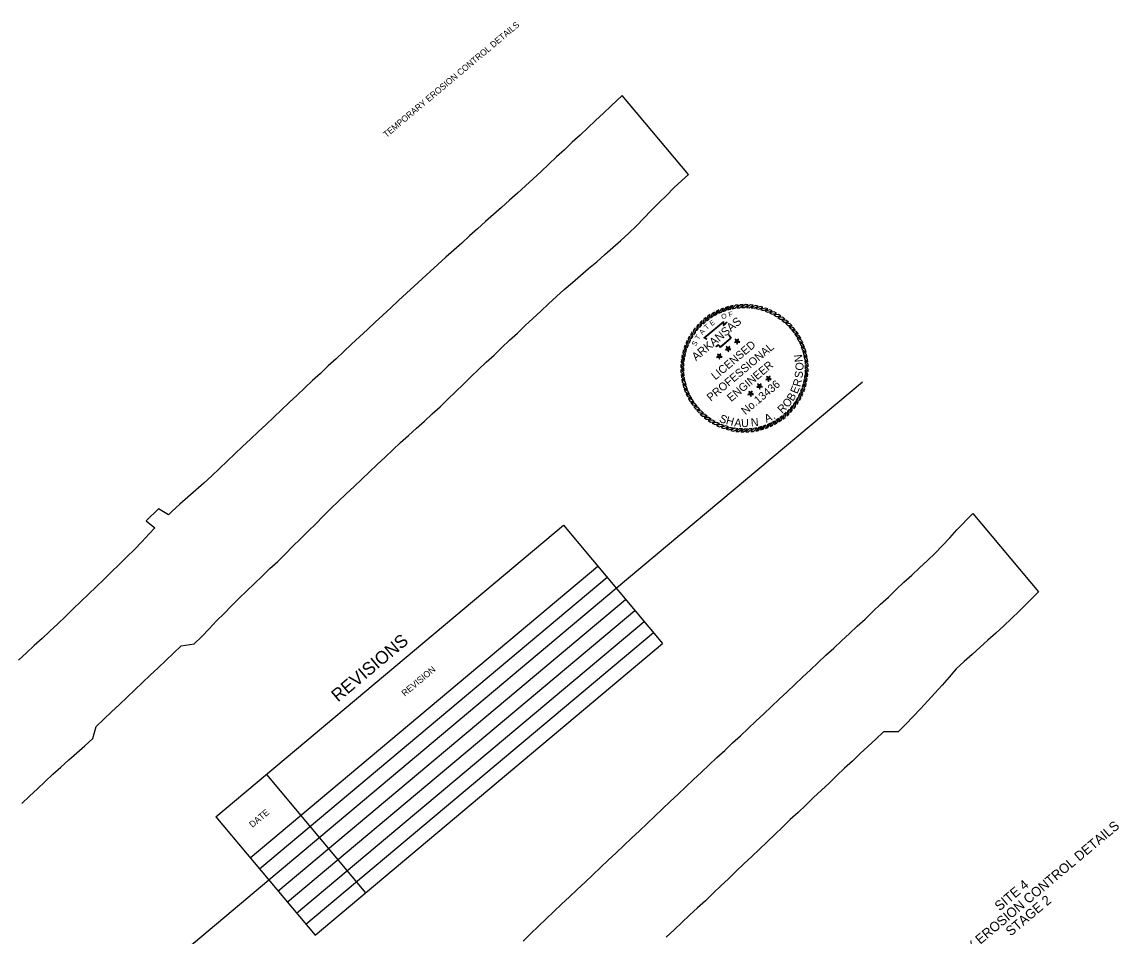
# Model space of a CAD drawing. Extents: x 1430270 to 1431940, y 1964631 to 1966264.
# Drawn here: x 1430913 to 1431940, y 1965408 to 1966264 of the extents above; entities that cross this region are included whole.
import ezdxf

# ---------------------------------------------------------------- set-up
doc = ezdxf.new("R2010")
doc.units = 0
for name, color, linetype in [('1', 7, 'Continuous'), ('60', 7, 'Continuous'), ('Default', 7, 'Continuous'), ('G-ANNO-SYMB', 7, 'Continuous'), ('R_NO PLOT', 7, 'Continuous')]:
    doc.layers.add(name, color=color, linetype=linetype)

msp = doc.modelspace()

# ---------------------------------------------------------------- linework, layer by layer
at = {"layer": '1'}
for p, q in [((1431469.3, 1965733.3), (1431699.9, 1965926.7)), ((1430924.6, 1965276.1), (1431143.8, 1965460.1))]:
    msp.add_line(p, q, dxfattribs=at)
at = {"layer": 'Default'}
for p, q in [((1431094.3, 1965519.1), (1431419.9, 1965792.3)), ((1431419.9, 1965792.3), (1431512.7, 1965681.6)), ((1431126.4, 1965480.8), (1431452, 1965754)), ((1431135.1, 1965470.4), (1431460.7, 1965743.6)), ((1431143.8, 1965460.1), (1431469.3, 1965733.3)), ((1431152.5, 1965449.7), (1431478, 1965722.9)), ((1431152.5, 1965449.7), (1431478, 1965722.9)), ((1431161.1, 1965439.4), (1431486.7, 1965712.6)), ((1431169.8, 1965429.1), (1431495.4, 1965702.2)), ((1431178.5, 1965418.7), (1431504.1, 1965691.9)), ((1431187.2, 1965408.4), (1431512.7, 1965681.6)), ((1431141.6, 1965558.8), (1431234.5, 1965448.1)), ((1431094.3, 1965519.1), (1431187.2, 1965408.4))]:
    msp.add_line(p, q, dxfattribs=at)
at = {"layer": 'G-ANNO-SYMB'}
for points in [[(1431561.3, 1965992), (1431559.1, 1965990.7), (1431557.5, 1965986.5), (1431559.8, 1965988)], [(1431565.5, 1965994), (1431563.2, 1965992.9), (1431561.3, 1965988.8), (1431563.7, 1965990.1)], [(1431569.9, 1965995.7), (1431567.5, 1965994.8), (1431565.2, 1965990.9), (1431567.8, 1965992)], [(1431574.4, 1965997.1), (1431571.9, 1965996.4), (1431569.3, 1965992.6), (1431572, 1965993.5)], [(1431579, 1965998.1), (1431576.5, 1965997.6), (1431573.6, 1965994), (1431576.3, 1965994.8)], [(1431583.6, 1965998.7), (1431581.1, 1965998.4), (1431577.9, 1965995.1), (1431580.6, 1965995.6)], [(1431588.3, 1965999), (1431585.7, 1965998.9), (1431582.3, 1965995.9), (1431585.1, 1965996.1)], [(1431593, 1965998.9), (1431590.4, 1965999), (1431586.8, 1965996.2), (1431589.5, 1965996.3)], [(1431597.6, 1965998.5), (1431595.1, 1965998.8), (1431591.2, 1965996.3), (1431594, 1965996.1)], [(1431602.2, 1965997.6), (1431599.7, 1965998.1), (1431595.7, 1965996), (1431598.5, 1965995.6)], [(1431606.8, 1965996.5), (1431604.3, 1965997.2), (1431600.1, 1965995.3), (1431602.8, 1965994.7)], [(1431611.2, 1965994.9), (1431608.8, 1965995.8), (1431604.5, 1965994.3), (1431607.1, 1965993.5)], [(1431615.5, 1965993.1), (1431613.2, 1965994.1), (1431608.7, 1965992.9), (1431611.3, 1965991.9)], [(1431619.6, 1965990.9), (1431617.4, 1965992.1), (1431612.9, 1965991.3), (1431615.4, 1965990.1)], [(1431546.5, 1965980.7), (1431544.7, 1965978.8), (1431544.5, 1965974.3), (1431546.2, 1965976.4)], [(1431549.8, 1965984), (1431547.9, 1965982.2), (1431547.4, 1965977.7), (1431549.3, 1965979.7)], [(1431553.5, 1965986.9), (1431551.4, 1965985.3), (1431550.5, 1965980.9), (1431552.6, 1965982.7)], [(1431557.3, 1965989.6), (1431555.2, 1965988.2), (1431553.9, 1965983.8), (1431556.1, 1965985.5)], [(1431623.6, 1965988.3), (1431621.4, 1965989.7), (1431616.9, 1965989.3), (1431619.3, 1965987.9)], [(1431627.3, 1965985.5), (1431625.3, 1965987.1), (1431620.7, 1965987), (1431623, 1965985.4)], [(1431630.8, 1965982.4), (1431628.9, 1965984.1), (1431624.4, 1965984.4), (1431626.5, 1965982.6)], [(1431634.1, 1965979), (1431632.3, 1965980.9), (1431627.8, 1965981.5), (1431629.8, 1965979.6)], [(1431540.5, 1965973.5), (1431539.1, 1965971.3), (1431539.6, 1965966.8), (1431541, 1965969.2)], [(1431543.3, 1965977.2), (1431541.8, 1965975.2), (1431541.9, 1965970.6), (1431543.5, 1965972.9)], [(1431637, 1965975.4), (1431635.4, 1965977.4), (1431631, 1965978.4), (1431632.8, 1965976.3)], [(1431639.7, 1965971.5), (1431638.3, 1965973.7), (1431633.9, 1965975), (1431635.6, 1965972.8)], [(1431642.1, 1965967.5), (1431640.8, 1965969.7), (1431636.6, 1965971.4), (1431638.1, 1965969.1)], [(1431533.9, 1965961.1), (1431533, 1965958.7), (1431534.6, 1965954.4), (1431535.3, 1965957)], [(1431535.8, 1965965.4), (1431534.7, 1965963.1), (1431535.9, 1965958.6), (1431536.9, 1965961.2)], [(1431538, 1965969.5), (1431536.7, 1965967.3), (1431537.6, 1965962.8), (1431538.8, 1965965.3)], [(1431574.2, 1965957.6), (1431574.1, 1965958.6), (1431572.4, 1965959.7), (1431573.2, 1965957.8)], [(1431574.2, 1965957.6), (1431575.2, 1965958), (1431575.6, 1965959.9), (1431574.1, 1965958.6)], [(1431582.6, 1965964.6), (1431581.5, 1965964.8), (1431580, 1965963.6), (1431582, 1965963.7)], [(1431582.6, 1965964.6), (1431582.5, 1965965.6), (1431580.8, 1965966.7), (1431581.5, 1965964.8)], [(1431582.6, 1965964.6), (1431582, 1965963.7), (1431582.7, 1965961.9), (1431583.2, 1965963.8)], [(1431582.6, 1965964.6), (1431583.5, 1965965), (1431584, 1965966.9), (1431582.5, 1965965.6)], [(1431582.6, 1965964.6), (1431583.2, 1965963.8), (1431585.2, 1965963.9), (1431583.5, 1965965)], [(1431644.1, 1965963.3), (1431643, 1965965.6), (1431638.9, 1965967.6), (1431640.2, 1965965.2)], [(1431645.8, 1965958.9), (1431644.9, 1965961.3), (1431641, 1965963.6), (1431642.1, 1965961.1)], [(1431531.2, 1965952.1), (1431530.7, 1965949.6), (1431532.9, 1965945.6), (1431533.2, 1965948.4)], [(1431532.4, 1965956.7), (1431531.7, 1965954.2), (1431533.5, 1965950), (1431534.1, 1965952.7)], [(1431565.8, 1965950.6), (1431564.8, 1965950.8), (1431563.3, 1965949.5), (1431565.3, 1965949.7)], [(1431565.8, 1965950.6), (1431565.8, 1965951.6), (1431564.1, 1965952.6), (1431564.8, 1965950.8)], [(1431565.8, 1965950.6), (1431565.3, 1965949.7), (1431566, 1965947.8), (1431566.5, 1965949.8)], [(1431565.8, 1965950.6), (1431566.8, 1965951), (1431567.3, 1965952.9), (1431565.8, 1965951.6)], [(1431565.8, 1965950.6), (1431566.5, 1965949.8), (1431568.5, 1965949.9), (1431566.8, 1965951)], [(1431574.2, 1965957.6), (1431573.2, 1965957.8), (1431571.7, 1965956.6), (1431573.6, 1965956.7)], [(1431574.2, 1965957.6), (1431573.6, 1965956.7), (1431574.4, 1965954.9), (1431574.9, 1965956.8)], [(1431574.2, 1965957.6), (1431574.9, 1965956.8), (1431576.8, 1965956.9), (1431575.2, 1965958)], [(1431647.2, 1965954.4), (1431646.5, 1965956.9), (1431642.7, 1965959.5), (1431643.6, 1965956.9)], [(1431648.2, 1965949.9), (1431647.7, 1965952.4), (1431644.1, 1965955.3), (1431644.8, 1965952.6)], [(1431648.8, 1965945.2), (1431648.5, 1965947.8), (1431645.2, 1965950.9), (1431645.7, 1965948.2)], [(1431529.9, 1965942.9), (1431529.8, 1965940.3), (1431532.6, 1965936.7), (1431532.5, 1965939.5)], [(1431530.4, 1965947.5), (1431530.1, 1965945), (1431532.6, 1965941.2), (1431532.7, 1965943.9)], [(1431649.1, 1965940.6), (1431649, 1965943.1), (1431646, 1965946.5), (1431646.2, 1965943.8)], [(1431649, 1965935.9), (1431649.1, 1965938.4), (1431646.3, 1965942.1), (1431646.4, 1965939.3)], [(1431529.8, 1965938.2), (1431529.9, 1965935.6), (1431533, 1965932.2), (1431532.7, 1965935)], [(1431530.1, 1965933.5), (1431530.4, 1965931), (1431533.7, 1965927.8), (1431533.2, 1965930.5)], [(1431530.7, 1965928.9), (1431531.2, 1965926.4), (1431534.8, 1965923.5), (1431534.1, 1965926.2)], [(1431611.9, 1965929.6), (1431610.9, 1965929.8), (1431609.4, 1965928.6), (1431611.4, 1965928.7)], [(1431611.9, 1965929.6), (1431611.8, 1965930.6), (1431610.2, 1965931.7), (1431610.9, 1965929.8)], [(1431611.9, 1965929.6), (1431611.4, 1965928.7), (1431612.1, 1965926.9), (1431612.6, 1965928.8)], [(1431611.9, 1965929.6), (1431612.9, 1965930), (1431613.4, 1965931.9), (1431611.8, 1965930.6)], [(1431611.9, 1965929.6), (1431612.6, 1965928.8), (1431614.6, 1965928.9), (1431612.9, 1965930)], [(1431647.7, 1965926.6), (1431648.2, 1965929.1), (1431646.1, 1965933.1), (1431645.7, 1965930.4)], [(1431648.6, 1965931.2), (1431648.9, 1965933.8), (1431646.4, 1965937.6), (1431646.2, 1965934.8)], [(1431531.7, 1965924.3), (1431532.4, 1965921.8), (1431536.2, 1965919.2), (1431535.3, 1965921.9)], [(1431533.1, 1965919.8), (1431534, 1965917.4), (1431538, 1965915.1), (1431536.8, 1965917.7)], [(1431603.6, 1965922.6), (1431602.6, 1965922.8), (1431601, 1965921.6), (1431603, 1965921.7)], [(1431603.6, 1965922.6), (1431603.5, 1965923.6), (1431601.8, 1965924.7), (1431602.6, 1965922.8)], [(1431603.6, 1965922.6), (1431603, 1965921.7), (1431603.8, 1965919.9), (1431604.2, 1965921.8)], [(1431603.6, 1965922.6), (1431604.5, 1965923), (1431605, 1965924.9), (1431603.5, 1965923.6)], [(1431603.6, 1965922.6), (1431604.2, 1965921.8), (1431606.2, 1965921.9), (1431604.5, 1965923)], [(1431643.2, 1965913.3), (1431644.2, 1965915.7), (1431643, 1965920.1), (1431642, 1965917.5)], [(1431645, 1965917.6), (1431645.9, 1965920.1), (1431644.4, 1965924.4), (1431643.6, 1965921.7)], [(1431646.6, 1965922.1), (1431647.3, 1965924.5), (1431645.4, 1965928.7), (1431644.8, 1965926)], [(1431534.8, 1965915.5), (1431535.9, 1965913.1), (1431540, 1965911.2), (1431538.7, 1965913.6)], [(1431536.9, 1965911.2), (1431538.1, 1965909), (1431542.4, 1965907.4), (1431540.9, 1965909.7)], [(1431595.2, 1965915.6), (1431594.2, 1965915.8), (1431592.7, 1965914.5), (1431594.7, 1965914.7)], [(1431595.2, 1965915.6), (1431595.1, 1965916.6), (1431593.5, 1965917.7), (1431594.2, 1965915.8)], [(1431595.2, 1965915.6), (1431594.7, 1965914.7), (1431595.4, 1965912.8), (1431595.9, 1965914.8)], [(1431595.2, 1965915.6), (1431596.2, 1965916), (1431596.7, 1965917.9), (1431595.1, 1965916.6)], [(1431595.2, 1965915.6), (1431595.9, 1965914.8), (1431597.9, 1965914.9), (1431596.2, 1965916)], [(1431638.4, 1965905.3), (1431639.8, 1965907.4), (1431639.4, 1965912), (1431638, 1965909.6)], [(1431640.9, 1965909.2), (1431642.2, 1965911.5), (1431641.4, 1965916), (1431640.2, 1965913.5)], [(1431539.2, 1965907.2), (1431540.7, 1965905.1), (1431545, 1965903.8), (1431543.4, 1965906)], [(1431541.9, 1965903.4), (1431543.5, 1965901.3), (1431548, 1965900.4), (1431546.1, 1965902.5)], [(1431544.9, 1965899.7), (1431546.6, 1965897.9), (1431551.2, 1965897.3), (1431549.2, 1965899.2)], [(1431629.1, 1965894.8), (1431631, 1965896.5), (1431631.6, 1965901.1), (1431629.7, 1965899.1)], [(1431632.5, 1965898), (1431634.2, 1965899.9), (1431634.5, 1965904.5), (1431632.7, 1965902.3)], [(1431635.6, 1965901.5), (1431637.2, 1965903.6), (1431637.1, 1965908.1), (1431635.5, 1965905.8)], [(1431548.1, 1965896.4), (1431550, 1965894.6), (1431554.6, 1965894.4), (1431552.4, 1965896.1)], [(1431551.6, 1965893.2), (1431553.6, 1965891.7), (1431558.2, 1965891.8), (1431555.9, 1965893.4)], [(1431555.4, 1965890.4), (1431557.5, 1965889), (1431562.1, 1965889.5), (1431559.7, 1965890.9)], [(1431559.3, 1965887.9), (1431561.6, 1965886.6), (1431566.1, 1965887.5), (1431563.6, 1965888.7)], [(1431609, 1965883), (1431611.4, 1965883.9), (1431613.7, 1965887.9), (1431611.2, 1965886.7)], [(1431613.4, 1965884.7), (1431615.7, 1965885.8), (1431617.7, 1965889.9), (1431615.2, 1965888.6)], [(1431617.6, 1965886.8), (1431619.8, 1965888), (1431621.5, 1965892.3), (1431619.1, 1965890.8)], [(1431621.6, 1965889.1), (1431623.8, 1965890.6), (1431625.1, 1965894.9), (1431622.9, 1965893.3)], [(1431625.5, 1965891.8), (1431627.5, 1965893.4), (1431628.4, 1965897.9), (1431626.4, 1965896)], [(1431563.4, 1965885.7), (1431565.8, 1965884.6), (1431570.2, 1965885.8), (1431567.6, 1965886.8)], [(1431567.7, 1965883.8), (1431570.1, 1965882.9), (1431574.5, 1965884.5), (1431571.8, 1965885.3)], [(1431572.2, 1965882.3), (1431574.6, 1965881.6), (1431578.8, 1965883.4), (1431576.1, 1965884)], [(1431576.7, 1965881.1), (1431579.2, 1965880.6), (1431583.2, 1965882.8), (1431580.5, 1965883.2)], [(1431581.3, 1965880.3), (1431583.9, 1965880), (1431587.7, 1965882.5), (1431584.9, 1965882.6)], [(1431586, 1965879.8), (1431588.5, 1965879.7), (1431592.2, 1965882.5), (1431589.4, 1965882.4)], [(1431590.7, 1965879.7), (1431593.2, 1965879.8), (1431596.6, 1965882.9), (1431593.9, 1965882.6)], [(1431595.3, 1965880), (1431597.9, 1965880.3), (1431601, 1965883.6), (1431598.3, 1965883.1)], [(1431600, 1965880.6), (1431602.5, 1965881.2), (1431605.4, 1965884.7), (1431602.7, 1965884)], [(1431604.5, 1965881.7), (1431607, 1965882.4), (1431609.6, 1965886.1), (1431607, 1965885.2)]]:
    msp.add_lwpolyline(points, close=True, dxfattribs=at)
for points in [[(1431554.3, 1965966.4), (1431551.3, 1965967.8), (1431569.7, 1965983.3), (1431569.8, 1965980.1), (1431571.1, 1965981.1), (1431572.1, 1965982), (1431573.2, 1965982.8)], [(1431554.5, 1965966.7), (1431552, 1965967.9), (1431569.4, 1965982.5), (1431569.5, 1965979.3), (1431571.3, 1965980.8), (1431572.3, 1965981.7), (1431573.4, 1965982.5)], [(1431575.3, 1965970.8), (1431575.2, 1965970.3), (1431575.4, 1965969.8), (1431576.1, 1965968.8), (1431577.1, 1965967.5), (1431566.9, 1965958.9), (1431565.4, 1965960.6), (1431565.1, 1965961), (1431564.6, 1965960.7), (1431563.1, 1965959.5), (1431562.5, 1965959.7)], [(1431574.9, 1965970.9), (1431574.8, 1965970.2), (1431575, 1965969.6), (1431575.8, 1965968.5), (1431576.6, 1965967.6), (1431566.9, 1965959.4), (1431565.7, 1965960.8), (1431565.2, 1965961.4), (1431564.4, 1965961.1), (1431563, 1965959.9), (1431562.6, 1965960.1)]]:
    msp.add_lwpolyline(points, dxfattribs=at)
at = {"layer": 'R_NO PLOT'}
msp.add_line((1431049.8, 1965802.1), (1431040.7, 1965807.8), dxfattribs=at)
for points in [[(1431537, 1966121), (1431474.9, 1966194.9), (1431464.6, 1966185.2), (1431457.3, 1966178.3), (1431450, 1966171.5), (1431442.7, 1966164.6), (1431435.4, 1966157.8), (1431428.1, 1966151), (1431420.8, 1966144.1), (1431413.5, 1966137.3), (1431406.2, 1966130.5), (1431398.9, 1966123.7), (1431391.5, 1966116.9), (1431384.2, 1966110.1), (1431376.8, 1966103.4), (1431369.3, 1966096.7), (1431361.9, 1966090.1), (1431354.4, 1966083.4), (1431346.9, 1966076.7), (1431339.4, 1966070.1), (1431332, 1966063.4), (1431324.6, 1966056.7), (1431317.1, 1966050.1), (1431309.7, 1966043.4), (1431302.2, 1966036.7), (1431294.9, 1966029.9), (1431287.5, 1966023.1), (1431280.2, 1966016.3), (1431272.8, 1966009.6), (1431265.5, 1966002.8), (1431258.2, 1965996), (1431250.8, 1965989.2), (1431243.5, 1965982.4), (1431236.2, 1965975.6), (1431228.8, 1965968.8), (1431221.4, 1965962), (1431214.1, 1965955.2), (1431206.9, 1965948.3), (1431199.5, 1965941.6), (1431192.3, 1965934.6), (1431184.9, 1965927.8), (1431177.7, 1965920.9), (1431170.4, 1965914.1), (1431163.1, 1965907.3), (1431155.9, 1965900.4), (1431148.6, 1965893.5), (1431141.3, 1965886.7), (1431134, 1965879.8), (1431126.7, 1965873), (1431119.4, 1965866.1), (1431112.2, 1965859.3), (1431104.9, 1965852.4), (1431097.6, 1965845.5), (1431090.4, 1965838.7), (1431083.1, 1965831.8), (1431075.7, 1965825.1), (1431068.1, 1965818.6), (1431060.5, 1965812), (1431053.1, 1965805.3), (1431049.8, 1965802.1)], [(1431061.9, 1965679.5), (1431074, 1965681.2), (1431081.2, 1965688.2), (1431088.1, 1965695.4), (1431095, 1965702.7), (1431102.1, 1965709.8), (1431109.1, 1965716.9), (1431116.1, 1965724), (1431123.3, 1965731), (1431130.6, 1965737.8), (1431137.8, 1965744.8), (1431145, 1965751.7), (1431152.3, 1965758.5), (1431159.4, 1965765.6), (1431166.5, 1965772.6), (1431173.7, 1965779.6), (1431180.7, 1965786.7), (1431187.8, 1965793.8), (1431194.9, 1965800.8), (1431202, 1965807.9), (1431209.2, 1965814.8), (1431216.5, 1965821.7), (1431223.7, 1965828.5), (1431231, 1965835.4), (1431238.3, 1965842.3), (1431245.5, 1965849.2), (1431252.8, 1965856), (1431260.1, 1965862.9), (1431267.4, 1965869.7), (1431274.7, 1965876.5), (1431282.1, 1965883.2), (1431289.6, 1965889.9), (1431297, 1965896.6), (1431304.3, 1965903.4), (1431311.5, 1965910.4), (1431318.8, 1965917.3), (1431325.9, 1965924.2), (1431333.1, 1965931.2), (1431340.4, 1965938.1), (1431347.6, 1965945), (1431354.9, 1965951.8), (1431362.1, 1965958.7), (1431369.4, 1965965.6), (1431376.7, 1965972.4), (1431384, 1965979.3), (1431391.3, 1965986.1), (1431398.6, 1965993), (1431405.9, 1965999.8), (1431413.3, 1966006.5), (1431420.7, 1966013.2), (1431428.3, 1966019.7), (1431435.8, 1966026.4), (1431443.4, 1966032.9), (1431451.3, 1966039.1), (1431458.7, 1966045.8), (1431466.2, 1966052.5), (1431473.6, 1966059.1), (1431481.1, 1966065.8), (1431488.2, 1966072.9), (1431495.1, 1966080.1), (1431502.2, 1966087.2), (1431509.3, 1966094.2), (1431516.3, 1966101.3), (1431523.4, 1966108.4), (1431530.7, 1966115.2), (1431537, 1966121)], [(1431040.7, 1965807.8), (1431028.9, 1965796.6), (1431037, 1965789.8)], [(1431382.1, 1965402.9), (1431389.2, 1965409.9), (1431396.5, 1965416.8), (1431403.7, 1965423.7), (1431410.9, 1965430.7), (1431418.2, 1965437.5), (1431425.5, 1965444.3), (1431432.8, 1965451.1), (1431440.1, 1965458), (1431447.4, 1965464.9), (1431454.6, 1965471.7), (1431461.9, 1965478.6), (1431469.2, 1965485.4), (1431476.5, 1965492.3), (1431483.7, 1965499.2), (1431491, 1965506.1), (1431498.2, 1965513), (1431505.5, 1965519.8), (1431512.7, 1965526.7), (1431520, 1965533.6), (1431527.3, 1965540.5), (1431534.5, 1965547.4), (1431541.8, 1965554.2), (1431549.1, 1965561), (1431556.4, 1965567.9), (1431563.7, 1965574.7), (1431571, 1965581.5), (1431578.3, 1965588.4), (1431585.6, 1965595.2), (1431592.9, 1965602.1), (1431600.2, 1965608.9), (1431607.5, 1965615.7), (1431614.8, 1965622.6), (1431622, 1965629.4), (1431629.3, 1965636.3), (1431636.6, 1965643.2), (1431643.9, 1965650), (1431651.2, 1965656.9), (1431658.5, 1965663.7), (1431665.8, 1965670.5), (1431673.1, 1965677.3), (1431680.4, 1965684.1), (1431687.8, 1965690.9), (1431695.1, 1965697.7), (1431702.4, 1965704.5), (1431709.6, 1965711.5), (1431716.9, 1965718.3), (1431724.3, 1965725.1), (1431731.5, 1965732.1), (1431738.6, 1965739), (1431746.1, 1965745.7), (1431753.5, 1965752.4), (1431760.8, 1965759.2), (1431768.1, 1965766.1), (1431775, 1965773.3), (1431781.9, 1965780.6), (1431788.5, 1965788.1), (1431803.3, 1965803.5), (1431864.9, 1965730.1)], [(1431037, 1965789.8), (1431031.7, 1965784.2), (1431024.9, 1965776.9), (1431018, 1965769.7), (1431010.8, 1965762.7), (1431003.6, 1965755.7), (1430996.5, 1965748.7), (1430989.4, 1965741.6), (1430982.2, 1965734.7), (1430975.1, 1965727.7), (1430967.8, 1965720.8), (1430960.6, 1965713.9), (1430953.4, 1965706.9), (1430946.2, 1965700.1), (1430938.8, 1965693.2), (1430931.5, 1965686.4), (1430924.2, 1965679.7), (1430916.8, 1965672.9), (1430909.5, 1965666.1)], [(1431864.9, 1965730.1), (1431853.9, 1965719), (1431846.7, 1965712), (1431839.5, 1965705.1), (1431832.3, 1965698.1), (1431824.9, 1965691.4), (1431817.5, 1965684.7), (1431810.1, 1965678), (1431802.6, 1965671.3), (1431795.1, 1965664.7), (1431787.7, 1965658), (1431781.3, 1965650.2), (1431774.6, 1965642.7), (1431767.9, 1965635.2), (1431761.2, 1965627.8), (1431754.3, 1965620.5), (1431747.5, 1965613.1), (1431740.6, 1965605.9), (1431733.4, 1965599), (1431719.6, 1965599)], [(1430982.1, 1965603.8), (1430989.3, 1965610.7), (1430996.6, 1965617.6), (1431003.9, 1965624.4), (1431011.1, 1965631.3), (1431018.4, 1965638.2), (1431025.7, 1965645.1), (1431032.9, 1965651.9), (1431040.2, 1965658.8), (1431047.4, 1965665.7), (1431054.7, 1965672.6), (1431061.9, 1965679.5)], [(1430912.7, 1965531.7), (1430919.8, 1965538.7), (1430927.1, 1965545.5), (1430934.4, 1965552.4), (1430941.7, 1965559.1), (1430949.2, 1965565.8), (1430956.6, 1965572.5), (1430964.1, 1965579.2), (1430971.6, 1965585.8), (1430979, 1965592.5), (1430982.1, 1965603.8)], [(1431719.6, 1965599), (1431712.4, 1965592.1), (1431705.1, 1965585.2), (1431697.8, 1965578.4), (1431690.5, 1965571.5), (1431683.3, 1965564.7), (1431676, 1965557.8), (1431668.7, 1965550.9), (1431661.5, 1965544.1), (1431654.2, 1965537.2), (1431646.9, 1965530.3), (1431639.7, 1965523.4), (1431632.4, 1965516.6), (1431625.2, 1965509.7), (1431617.9, 1965502.8), (1431610.7, 1965495.8), (1431603.5, 1965488.9), (1431596.2, 1965482), (1431589, 1965475.1), (1431581.8, 1965468.2), (1431574.5, 1965461.3), (1431567.3, 1965454.5), (1431560, 1965447.6), (1431552.8, 1965440.7), (1431545.4, 1965433.9), (1431538.1, 1965427), (1431530.8, 1965420.2), (1431523.5, 1965413.4), (1431516.2, 1965406.5)]]:
    msp.add_lwpolyline(points, dxfattribs=at)

# ---------------------------------------------------------------- texts
at = {"layer": '1'}
msp.add_text('TEMPORARY EROSION CONTROL DETAILS', height=5.862, rotation=40, dxfattribs=at).set_placement((1431254.1, 1966155.1))
at = {"layer": '60'}
for s, p in [('TEMPORARY EROSION CONTROL DETAILS', (1431749.4, 1965348.2)), ('SITE 4', (1431828.4, 1965430.6)), ('STAGE 2', (1431838.8, 1965407))]:
    msp.add_text(s, height=9, rotation=40, dxfattribs=at).set_placement(p)
at = {"layer": 'Default'}
for s, height, p in [('REVISIONS', 12, (1431208.7, 1965626.2)), ('REVISION', 6, (1431271.3, 1965631.7)), ('DATE', 6, (1431128.6, 1965508.7))]:
    msp.add_text(s, height=height, rotation=40, dxfattribs=at).set_placement(p)
at = {"layer": 'G-ANNO-SYMB'}
for s, height, rotation, p in [('O', 4.75, 21.2218, (1431568.7, 1965985)), ('F', 4.75, 15.3628, (1431575.2, 1965987.2)), ('ARKANSAS', 7.75, 40, (1431544.1, 1965945.8)), ('T', 4.75, 41.4789, (1431554.1, 1965975)), ('E', 4.75, 36.672, (1431558.9, 1965978.8)), ('T', 4.75, 56.9015, (1431546.6, 1965965.5)), ('A', 4.75, 48.6788, (1431550, 1965970.4)), ('S', 4.75, 59.7726, (1431543.7, 1965959.6)), ('PROFESSIONAL', 7.5, 40, (1431558, 1965908)), ('LICENSED', 7.5, 40, (1431562.2, 1965928)), ('N', 7.5, 96.1007, (1431644.1, 1965945.5)), ('ENGINEER', 7.5, 40, (1431577, 1965907.6)), ('O', 7.5, 84.7757, (1431644.4, 1965936.9)), ('R', 7.5, 75.6597, (1431641.7, 1965921.5)), ('S', 7.5, 83.4878, (1431643.7, 1965929.8)), ('No.13436', 7.47, 40, (1431590.3, 1965895.4)), ('E', 7.5, 67.8315, (1431638.9, 1965914.9)), ('O', 7.5, 51.4296, (1431630.1, 1965901.9)), ('B', 7.5, 58.885, (1431634.9, 1965907.9)), ('R', 7.5, 43.2287, (1431624.6, 1965896.6)), ('S', 7.5, 338.1636, (1431565.2, 1965889.5)), ('H', 7.5, 345.619, (1431571.6, 1965887.2)), ('A', 7.5, 353.4472, (1431579.6, 1965885)), ('U', 7.5, 0.9026, (1431586.3, 1965884.3)), ('N', 7.5, 4.9326, (1431595.7, 1965884.8)), ('A', 7.5, 23.0991, (1431609.9, 1965888.3)), ('.', 7.5, 31.3, (1431616.9, 1965891.4))]:
    msp.add_text(s, height=height, rotation=rotation, dxfattribs=at).set_placement(p)

doc.saveas('drawing.dxf')
